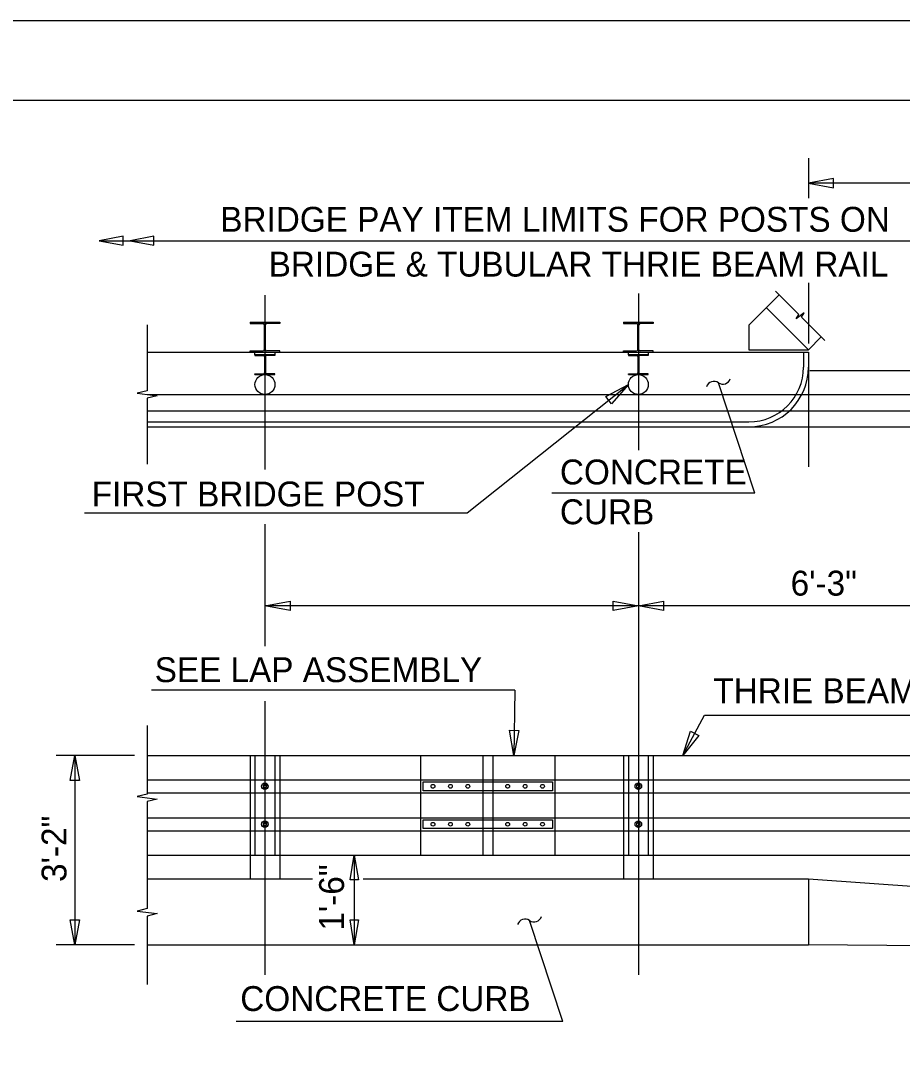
# Model space of a CAD drawing. Extents: x 0 to 22.7, y 0 to 15.7.
# Drawn here: x 11.159 to 14.849, y 10.354 to 14.667 of the extents above; entities that cross this region are included whole.
import ezdxf

# ---------------------------------------------------------------- set-up
doc = ezdxf.new("R2010")
doc.units = 0
for name, color, linetype in [('BORDER_ANNO_Cutsheet', 7, 'Continuous'), ('BRDG_ANNO_Anno-Sheet', 7, 'Continuous'), ('BRDG_ANNO_General-Notes', 7, 'Continuous'), ('BRDG_BASE_Active-Point', 7, 'Continuous'), ('BRDG_BASE_Dtlctrln', 7, 'Continuous'), ('BRDG_BASE_Hidden-Line', 7, 'Continuous'), ('BRDG_BASE_Obj-Line', 7, 'Continuous'), ('BRDG_BASE_Phtline', 7, 'Continuous'), ('BRDG_BASE_Rebar', 7, 'Continuous'), ('Default', 7, 'Continuous')]:
    doc.layers.add(name, color=color, linetype=linetype)

# ---------------------------------------------------------------- blocks, each defined once
blk = doc.blocks.new('TERM')
at = {"layer": 'Default'}
for p, q in [((-1.6, -0.267), (-1.6, 0.267)), ((-1.6, 0.267), (0, 0)), ((0, 0), (-1.6, -0.267))]:
    blk.add_line(p, q, dxfattribs=at)

msp = doc.modelspace()

# ---------------------------------------------------------------- linework, layer by layer
at = {"layer": 'BORDER_ANNO_Cutsheet'}
msp.add_lwpolyline([(0, 14.6667), (22.6667, 14.6667), (22.6667, 0), (0, 0)], close=True, dxfattribs=at)
at = {"layer": 'BRDG_ANNO_Anno-Sheet'}
msp.add_lwpolyline([(1, 14.3333), (22.3333, 14.3333), (22.3333, 0.3333), (1, 0.3333)], close=True, dxfattribs=at)
at = {"layer": 'BRDG_ANNO_General-Notes'}
for p, q in [((14.4561, 14.0907), (14.4561, 13.9234)), ((14.5611, 14.0061), (14.4561, 13.9864)), ((20.252, 13.9864), (14.4561, 13.9864)), ((14.4561, 13.9864), (14.5611, 13.9667)), ((14.5611, 13.9667), (14.5611, 14.0061)), ((11.588, 13.7643), (11.488, 13.7456)), ((11.588, 13.7268), (11.588, 13.7643)), ((11.7172, 13.7643), (11.6172, 13.7456)), ((11.7172, 13.7268), (11.7172, 13.7643)), ((11.488, 13.7456), (16.869, 13.7456)), ((11.488, 13.7456), (11.588, 13.7268)), ((11.6172, 13.7456), (11.7172, 13.7268)), ((14.4561, 13.5693), (14.4561, 13.3158)), ((13.027, 12.6071), (13.7023, 13.1439)), ((13.6078, 13.094), (13.7023, 13.1439)), ((13.7023, 13.1439), (13.6323, 13.0631)), ((14.2319, 12.6897), (14.079, 13.1515)), ((13.6323, 13.0631), (13.6078, 13.094)), ((14.2319, 12.6897), (13.3825, 12.6897)), ((11.4267, 12.6071), (13.027, 12.6071)), ((12.1815, 12.2181), (12.2865, 12.2378)), ((13.744, 12.2181), (12.1815, 12.2181)), ((12.2865, 12.1984), (12.1815, 12.2181)), ((12.2865, 12.2378), (12.2865, 12.1984)), ((13.639, 12.1984), (13.639, 12.2378)), ((13.639, 12.2378), (13.744, 12.2181)), ((13.744, 12.2181), (13.639, 12.1984)), ((13.744, 12.2181), (13.849, 12.2378)), ((15.3065, 12.2181), (13.744, 12.2181)), ((13.849, 12.1984), (13.744, 12.2181)), ((13.849, 12.2378), (13.849, 12.1984)), ((13.2272, 11.8649), (11.7061, 11.8649)), ((13.2272, 11.8649), (13.2229, 11.5918)), ((13.2049, 11.6971), (13.2443, 11.6965)), ((13.2229, 11.5918), (13.2049, 11.6971)), ((13.2443, 11.6965), (13.2229, 11.5918)), ((13.9298, 11.5918), (13.9622, 11.6935)), ((13.9622, 11.6935), (13.9969, 11.6749)), ((13.9969, 11.6749), (13.9298, 11.5918)), ((11.6361, 11.5918), (11.308, 11.5918)), ((11.3861, 11.5918), (11.3861, 10.8001)), ((12.5549, 11.1751), (12.5549, 10.8001)), ((13.4285, 10.4789), (13.2886, 10.9013)), ((11.6361, 10.8001), (11.308, 10.8001)), ((13.4285, 10.4789), (12.0604, 10.4789))]:
    msp.add_line(p, q, dxfattribs=at)
for points in [[(13.9298, 11.5918), (14.0208, 11.7608)], [(14.0208, 11.7608), (15.8765, 11.7608)]]:
    msp.add_lwpolyline(points, dxfattribs=at)
for centre, start, end in [((14.0602, 13.1245), 55.1987, 161.4589), ((14.0977, 13.1784), 235.1987, 341.4589), ((13.3074, 10.9282), 235.1987, 341.4589), ((13.2699, 10.8744), 55.1987, 161.4589)]:
    msp.add_arc(centre, 0.0328, start, end, dxfattribs=at)
at = {"layer": 'BRDG_BASE_Active-Point'}
for p, q in [((12.119, 13.4043), (12.244, 13.4043)), ((12.119, 13.4043), (12.119, 13.3991)), ((12.119, 13.3991), (12.1736, 13.3991)), ((12.1789, 13.2897), (12.1789, 13.3939)), ((12.1841, 13.2897), (12.1841, 13.3939)), ((12.244, 13.3991), (12.1893, 13.3991)), ((12.244, 13.4043), (12.244, 13.3991)), ((13.6815, 13.4043), (13.8065, 13.4043)), ((13.6815, 13.4043), (13.6815, 13.3991)), ((13.6815, 13.3991), (13.7361, 13.3991)), ((13.7414, 13.2897), (13.7414, 13.3939)), ((13.7466, 13.2897), (13.7466, 13.3939)), ((13.8065, 13.3991), (13.7518, 13.3991)), ((13.8065, 13.4043), (13.8065, 13.3991)), ((12.1815, 13.3418), (12.1815, 13.3418)), ((13.744, 13.3418), (13.744, 13.3418)), ((12.119, 13.2793), (12.119, 13.2845)), ((12.119, 13.2845), (12.1736, 13.2845)), ((12.244, 13.2845), (12.1893, 13.2845)), ((12.244, 13.2793), (12.244, 13.2845)), ((13.6815, 13.2793), (13.6815, 13.2845)), ((13.6815, 13.2845), (13.7361, 13.2845)), ((13.8065, 13.2845), (13.7518, 13.2845)), ((13.8065, 13.2793), (13.8065, 13.2845)), ((12.119, 13.2793), (12.244, 13.2793)), ((12.1398, 13.2689), (12.2231, 13.2689)), ((12.1398, 13.2689), (12.1398, 13.2654)), ((12.1398, 13.2654), (12.1762, 13.2654)), ((12.1797, 13.2619), (12.1797, 13.1924)), ((12.1832, 13.2619), (12.1832, 13.1924)), ((12.2231, 13.2654), (12.1867, 13.2654)), ((12.2231, 13.2689), (12.2231, 13.2654)), ((13.6815, 13.2793), (13.8065, 13.2793)), ((13.7023, 13.2689), (13.7856, 13.2689)), ((13.7023, 13.2689), (13.7023, 13.2654)), ((13.7023, 13.2654), (13.7387, 13.2654)), ((13.7422, 13.2619), (13.7422, 13.1924)), ((13.7457, 13.2619), (13.7457, 13.1924)), ((13.7856, 13.2654), (13.7492, 13.2654)), ((13.7856, 13.2689), (13.7856, 13.2654)), ((12.1815, 13.2272), (12.1815, 13.2272)), ((13.744, 13.2272), (13.744, 13.2272)), ((12.1398, 13.1855), (12.1398, 13.189)), ((12.1398, 13.189), (12.1762, 13.189)), ((12.1398, 13.1855), (12.2231, 13.1855)), ((12.2231, 13.189), (12.1867, 13.189)), ((12.2231, 13.1855), (12.2231, 13.189)), ((13.7023, 13.1855), (13.7023, 13.189)), ((13.7023, 13.189), (13.7387, 13.189)), ((13.7023, 13.1855), (13.7856, 13.1855)), ((13.7856, 13.189), (13.7492, 13.189)), ((13.7856, 13.1855), (13.7856, 13.189))]:
    msp.add_line(p, q, dxfattribs=at)
for centre, radius, start, end in [((12.1736, 13.3938), 0.00521, 0, 90), ((12.1893, 13.3938), 0.00521, 90, 180), ((13.7361, 13.3938), 0.00521, 0, 90), ((13.7518, 13.3938), 0.00521, 90, 180), ((12.1736, 13.2897), 0.00521, 270, 360), ((12.1893, 13.2897), 0.00521, 180, 270), ((13.7361, 13.2897), 0.00521, 270, 360), ((13.7518, 13.2897), 0.00521, 180, 270), ((12.1762, 13.2619), 0.00347, 0, 90), ((12.1867, 13.2619), 0.00347, 90, 180), ((13.7387, 13.2619), 0.00347, 0, 90), ((13.7492, 13.2619), 0.00347, 90, 180), ((12.1762, 13.1925), 0.00347, 270, 0), ((12.1867, 13.1925), 0.00347, 180, 270), ((13.7387, 13.1925), 0.00347, 270, 0), ((13.7492, 13.1925), 0.00347, 180, 270)]:
    msp.add_arc(centre, radius, start, end, dxfattribs=at)
at = {"layer": 'BRDG_BASE_Dtlctrln'}
for p, q in [((12.1815, 13.5179), (12.1815, 12.7886)), ((13.744, 13.5246), (13.744, 12.8697)), ((12.1815, 12.5595), (12.1815, 12.0492)), ((13.744, 12.526), (13.744, 10.6736)), ((12.1815, 11.8193), (12.1815, 10.6736))]:
    msp.add_line(p, q, dxfattribs=at)
at = {"layer": 'BRDG_BASE_Hidden-Line'}
for centre in [(12.1813, 11.4629), (13.7439, 11.4629), (12.1813, 11.304), (13.7439, 11.304)]:
    msp.add_circle(centre, 0.00651, dxfattribs=at)
for centre in [(12.1813, 11.4629), (13.7439, 11.4629), (12.1813, 11.304), (13.7439, 11.304)]:
    msp.add_ellipse(centre, major_axis=(0, 0.00977), ratio=0.666667, dxfattribs=at)
at = {"layer": 'BRDG_BASE_Obj-Line'}
for p, q in [((14.2057, 13.3928), (14.3326, 13.5197)), ((14.2794, 13.4665), (14.4561, 13.2897)), ((12.119, 13.4043), (12.244, 13.4043)), ((12.119, 13.4043), (12.119, 13.3991)), ((12.119, 13.3991), (12.1736, 13.3991)), ((12.1789, 13.2897), (12.1789, 13.3939)), ((12.1841, 13.2897), (12.1841, 13.3939)), ((12.244, 13.3991), (12.1893, 13.3991)), ((12.244, 13.4043), (12.244, 13.3991)), ((13.6815, 13.4043), (13.8065, 13.4043)), ((13.6815, 13.4043), (13.6815, 13.3991)), ((13.6815, 13.3991), (13.7361, 13.3991)), ((13.7414, 13.2897), (13.7414, 13.3939)), ((13.7466, 13.2897), (13.7466, 13.3939)), ((13.8065, 13.3991), (13.7518, 13.3991)), ((13.8065, 13.4043), (13.8065, 13.3991)), ((14.2057, 13.3928), (14.2057, 13.2897)), ((12.1815, 13.3418), (12.1815, 13.3418)), ((13.744, 13.3418), (13.744, 13.3418)), ((14.4561, 13.2897), (14.5094, 13.3429)), ((12.119, 13.2793), (12.119, 13.2845)), ((12.119, 13.2845), (12.1736, 13.2845)), ((12.244, 13.2845), (12.1893, 13.2845)), ((12.244, 13.2793), (12.244, 13.2845)), ((13.6815, 13.2793), (13.6815, 13.2845)), ((13.6815, 13.2845), (13.7361, 13.2845)), ((13.8065, 13.2845), (13.7518, 13.2845)), ((13.8065, 13.2793), (13.8065, 13.2845)), ((14.2057, 13.2897), (14.4561, 13.2897)), ((11.6882, 13.2793), (14.4561, 13.2793)), ((12.119, 13.2793), (12.244, 13.2793)), ((12.1398, 13.2689), (12.2231, 13.2689)), ((12.1398, 13.2689), (12.1398, 13.2654)), ((12.1398, 13.2654), (12.1762, 13.2654)), ((12.1797, 13.2619), (12.1797, 13.1924)), ((12.1832, 13.2619), (12.1832, 13.1924)), ((12.2231, 13.2654), (12.1867, 13.2654)), ((12.2231, 13.2689), (12.2231, 13.2654)), ((13.6815, 13.2793), (13.8065, 13.2793)), ((13.7023, 13.2689), (13.7856, 13.2689)), ((13.7023, 13.2689), (13.7023, 13.2654)), ((13.7023, 13.2654), (13.7387, 13.2654)), ((13.7422, 13.2619), (13.7422, 13.1924)), ((13.7457, 13.2619), (13.7457, 13.1924)), ((13.7856, 13.2654), (13.7492, 13.2654)), ((13.7856, 13.2689), (13.7856, 13.2654)), ((14.4353, 13.2793), (14.4353, 13.2168)), ((14.4561, 13.2793), (14.4561, 12.8003)), ((12.1815, 13.2272), (12.1815, 13.2272)), ((13.744, 13.2272), (13.744, 13.2272)), ((12.1398, 13.1855), (12.1398, 13.189)), ((12.1398, 13.189), (12.1762, 13.189)), ((12.1398, 13.1855), (12.2231, 13.1855)), ((12.2231, 13.189), (12.1867, 13.189)), ((12.2231, 13.1855), (12.2231, 13.189)), ((13.7023, 13.1855), (13.7023, 13.189)), ((13.7023, 13.189), (13.7387, 13.189)), ((13.7023, 13.1855), (13.7856, 13.1855)), ((13.7856, 13.189), (13.7492, 13.189)), ((13.7856, 13.1855), (13.7856, 13.189)), ((11.6882, 12.9876), (14.2061, 12.9876)), ((11.6882, 12.9668), (14.2061, 12.9668)), ((11.6882, 11.0761), (12.3801, 11.0761)), ((12.5922, 11.0761), (14.4561, 11.0761)), ((14.4561, 11.0761), (14.4561, 10.8001)), ((11.6882, 10.8001), (14.4561, 10.8001))]:
    msp.add_line(p, q, dxfattribs=at)
for points in [[(14.5241, 13.3282), (14.4265, 13.4258), (14.4376, 13.4442), (14.421, 13.4313), (14.4044, 13.4184), (14.4155, 13.4368), (14.3179, 13.5344)], [(11.6882, 13.3939), (11.6882, 13.1178), (11.6465, 13.1074), (11.6882, 13.1022), (11.7298, 13.097), (11.6882, 13.0866), (11.6882, 12.8105)], [(11.6882, 11.7168), (11.6882, 11.4303), (11.6465, 11.4199), (11.7298, 11.4095), (11.6882, 11.3991), (11.6882, 11.1751), (11.6882, 10.9511), (11.6465, 10.9407), (11.7298, 10.9303), (11.6882, 10.9199), (11.6882, 10.6334)]]:
    msp.add_lwpolyline(points, dxfattribs=at)
for points in [[(12.1398, 13.2793), (12.2231, 13.2793), (12.2231, 13.2689), (12.1398, 13.2689)], [(13.7023, 13.2793), (13.7856, 13.2793), (13.7856, 13.2689), (13.7023, 13.2689)]]:
    msp.add_lwpolyline(points, close=True, dxfattribs=at)
for centre, radius in [((12.1815, 13.1439), 0.0417), ((13.744, 13.1439), 0.0417), ((12.1813, 11.4629), 0.0137), ((13.7439, 11.4629), 0.0137), ((12.1813, 11.304), 0.0137), ((13.7439, 11.304), 0.0137)]:
    msp.add_circle(centre, radius, dxfattribs=at)
for centre, radius, start, end in [((12.1736, 13.3938), 0.00521, 0, 90), ((12.1893, 13.3938), 0.00521, 90, 180), ((13.7361, 13.3938), 0.00521, 0, 90), ((13.7518, 13.3938), 0.00521, 90, 180), ((12.1736, 13.2897), 0.00521, 270, 360), ((12.1893, 13.2897), 0.00521, 180, 270), ((13.7361, 13.2897), 0.00521, 270, 360), ((13.7518, 13.2897), 0.00521, 180, 270), ((12.1762, 13.2619), 0.00347, 0, 90), ((12.1867, 13.2619), 0.00347, 90, 180), ((13.7387, 13.2619), 0.00347, 0, 90), ((13.7492, 13.2619), 0.00347, 90, 180), ((14.2061, 13.2168), 0.2292, 270, 360), ((14.2061, 13.2168), 0.25, 270, 360), ((12.1762, 13.1925), 0.00347, 270, 0), ((12.1867, 13.1925), 0.00347, 180, 270), ((13.7387, 13.1925), 0.00347, 270, 0), ((13.7492, 13.1925), 0.00347, 180, 270)]:
    msp.add_arc(centre, radius, start, end, dxfattribs=at)
at = {"layer": 'BRDG_BASE_Phtline'}
for p, q in [((15.0244, 13.2011), (14.4614, 13.2011)), ((11.6882, 13.1022), (16.7387, 13.1022)), ((11.6882, 13.0345), (16.7387, 13.0345)), ((11.6882, 12.9668), (16.7387, 12.9668)), ((11.6882, 11.5918), (16.7387, 11.5918)), ((12.8325, 11.5918), (12.8325, 11.1751)), ((13.0929, 11.5918), (13.0929, 11.1751)), ((13.1346, 11.5918), (13.1346, 11.1751)), ((13.395, 11.5918), (13.395, 11.1751)), ((11.6882, 11.4904), (16.7387, 11.4904)), ((11.6882, 11.4354), (16.7387, 11.4354)), ((11.6882, 11.3315), (16.7387, 11.3315)), ((11.6882, 11.2766), (16.7387, 11.2766)), ((11.6882, 11.1751), (16.7387, 11.1751)), ((14.4561, 11.0761), (15.0244, 11.0356)), ((15.0244, 10.794), (14.4561, 10.8001))]:
    msp.add_line(p, q, dxfattribs=at)
for points in [[(12.8429, 11.4811), (13.3846, 11.4811), (13.3846, 11.4446), (12.8429, 11.4446)], [(12.8429, 11.3222), (13.3846, 11.3222), (13.3846, 11.2858), (12.8429, 11.2858)]]:
    msp.add_lwpolyline(points, close=True, dxfattribs=at)
for centre in [(12.8846, 11.4629), (12.9575, 11.4629), (13.0304, 11.4629), (13.1971, 11.4629), (13.27, 11.4629), (13.3429, 11.4629), (12.8846, 11.304), (12.9575, 11.304), (13.0304, 11.304), (13.1971, 11.304), (13.27, 11.304), (13.3429, 11.304)]:
    msp.add_circle(centre, 0.00781, dxfattribs=at)
at = {"layer": 'BRDG_BASE_Rebar'}
for p, q in [((12.119, 11.5918), (12.119, 11.1751)), ((12.119, 11.5918), (12.244, 11.5918)), ((12.1398, 11.5918), (12.1398, 11.1751)), ((12.2231, 11.5918), (12.2231, 11.1751)), ((12.244, 11.5918), (12.244, 11.1751)), ((13.6815, 11.5918), (13.6815, 11.1751)), ((13.6815, 11.5918), (13.8065, 11.5918)), ((13.7023, 11.5918), (13.7023, 11.1751)), ((13.7856, 11.5918), (13.7856, 11.1751)), ((13.8065, 11.5918), (13.8065, 11.1751)), ((12.119, 11.1751), (12.119, 11.0761)), ((12.244, 11.1751), (12.244, 11.0761)), ((13.6815, 11.1751), (13.6815, 11.0761)), ((13.8065, 11.1751), (13.8065, 11.0761))]:
    msp.add_line(p, q, dxfattribs=at)

# ---------------------------------------------------------------- block references
at = {"layer": 'BRDG_ANNO_General-Notes', "xscale": 0.06510416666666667}
for p, yscale, rotation in [((11.3861, 11.5918), 0.0732421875, 90), ((12.5549, 11.1751), 0.06510416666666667, 90), ((11.3861, 10.8001), 0.0732421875, -90), ((12.5549, 10.8001), 0.06510416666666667, -90)]:
    msp.add_blockref('TERM', p, dxfattribs=dict(at, yscale=yscale, rotation=rotation))

# ---------------------------------------------------------------- texts
at = {"layer": 'BRDG_ANNO_General-Notes'}
for s, height, p in [('BRIDGE PAY ITEM LIMITS FOR POSTS ON', 0.104167, (11.9946, 13.7832)), ('BRIDGE & TUBULAR THRIE BEAM RAIL', 0.104167, (12.1972, 13.5957)), ('CONCRETE', 0.10417, (13.4158, 12.726)), ('FIRST BRIDGE POST', 0.104167, (11.4567, 12.6339)), ('CURB', 0.10417, (13.4158, 12.5594)), ('6\'-3"', 0.10417, (14.3813, 12.2608)), ('SEE LAP ASSEMBLY', 0.104167, (11.7201, 11.8987)), ('THRIE BEAM RETROFIT', 0.104167, (14.0579, 11.8107)), ('CONCRETE CURB', 0.104167, (12.0782, 10.5226))]:
    msp.add_text(s, height=height, dxfattribs=at).set_placement(p)
for s, p in [('3\'-2"', (11.351, 11.0627)), ('1\'-6"', (12.5123, 10.8588))]:
    msp.add_text(s, height=0.10417, rotation=90, dxfattribs=at).set_placement(p)

doc.saveas('drawing.dxf')
